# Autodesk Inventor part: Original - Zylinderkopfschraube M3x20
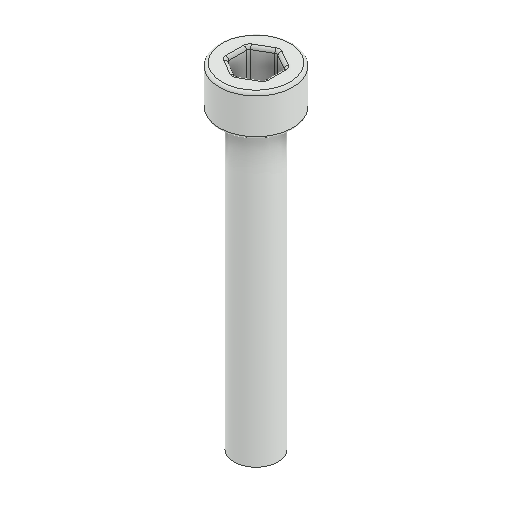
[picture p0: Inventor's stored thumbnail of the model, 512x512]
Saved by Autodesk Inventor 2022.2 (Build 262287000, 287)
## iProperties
Created: 2024-09
Part Number: Original - Zylinderkopfschraube M3x20
Material: Generico
Document SubType Name: Modeling
Designer: 18907419
Density: 1 g/cm^3
Appearance: Default
Author: 18907419
Revision Number: ANY
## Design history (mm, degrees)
feature "Verrundung3"
node "Solido1"
